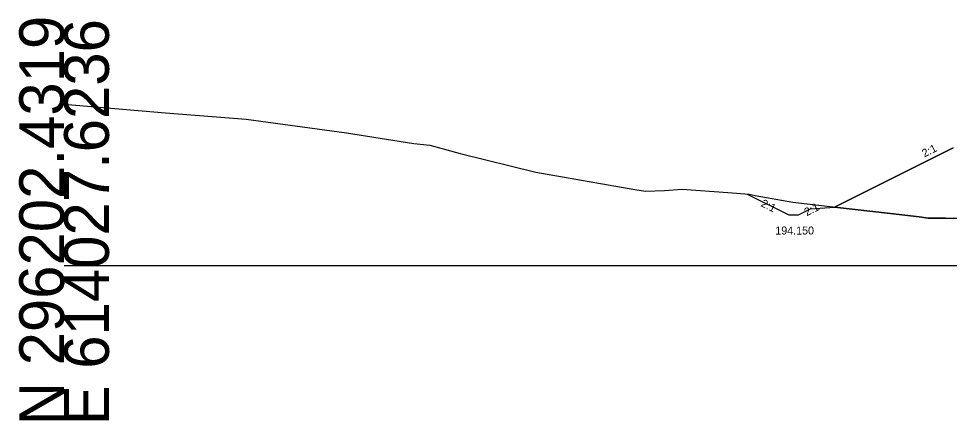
# Model space of a CAD drawing. Extents: x -81 to 616364, y 450 to 299952.
# Drawn here: x 541449.5 to 541507.7, y 118838.7 to 118863.8 of the extents above; entities that cross this region are included whole.
import ezdxf

# ---------------------------------------------------------------- set-up
doc = ezdxf.new("R2010")
doc.units = 0
for name, color, linetype in [('Exist XS Ground Line', 7, 'Continuous'), ('Old_Level_63', 7, 'Continuous'), ('Prop XS DDE', 7, 'Continuous'), ('Prop XS Earthwork Shape', 7, 'Continuous'), ('Prop XS Finish Grade Earthwork', 7, 'Continuous'), ('Prop XS Hydro Elevations', 7, 'Continuous'), ('Prop XS Side Slope Text', 7, 'Continuous')]:
    doc.layers.add(name, color=color, linetype=linetype)

msp = doc.modelspace()

# ---------------------------------------------------------------- linework, layer by layer
at = {"layer": 'Exist XS Ground Line'}
for p, q in [((541452.365, 118858.443), (541458.691, 118857.913)), ((541458.691, 118857.913), (541463.734, 118857.517)), ((541463.734, 118857.517), (541470.016, 118856.654)), ((541470.016, 118856.654), (541474.212, 118855.992)), ((541474.212, 118855.992), (541475.205, 118855.887)), ((541475.205, 118855.887), (541477.115, 118855.353)), ((541477.115, 118855.353), (541481.827, 118854.203)), ((541481.827, 118854.203), (541488.023, 118853.108)), ((541488.023, 118853.108), (541488.696, 118853.001)), ((541488.696, 118853.001), (541489.88, 118853.039)), ((541489.88, 118853.039), (541490.972, 118853.132)), ((541490.972, 118853.132), (541493.826, 118852.927)), ((541493.826, 118852.927), (541495.166, 118852.811)), ((541495.166, 118852.811), (541495.531, 118852.739)), ((541495.531, 118852.739), (541497.888, 118852.314)), ((541497.888, 118852.314), (541503.985, 118851.612)), ((541503.985, 118851.612), (541505.779, 118851.4)), ((541505.779, 118851.4), (541506.345, 118851.32)), ((541506.345, 118851.32), (541507.431, 118851.309)), ((541507.431, 118851.309), (541511.535, 118851.293))]:
    msp.add_line(p, q, dxfattribs=at)
at = {"layer": 'Old_Level_63'}
msp.add_line((541452.365, 118848.365), (541527.365, 118848.365), dxfattribs=at)
at = {"layer": 'Prop XS DDE'}
for p, q in [((541495.034, 118852.822), (541497.649, 118851.515)), ((541498.249, 118851.515), (541499.005, 118851.893)), ((541499.005, 118851.893), (541500.505, 118852.013)), ((541497.649, 118851.515), (541498.249, 118851.515))]:
    msp.add_line(p, q, dxfattribs=at)
at = {"layer": 'Prop XS Earthwork Shape'}
for points in [[(541507.915, 118855.718), (541500.505, 118852.013), (541503.985, 118851.612), (541505.779, 118851.4), (541506.345, 118851.32), (541507.431, 118851.309), (541511.535, 118851.293)], [(541507.915, 118855.718), (541500.505, 118852.013), (541503.985, 118851.612), (541505.779, 118851.4), (541506.345, 118851.32), (541507.431, 118851.309), (541511.535, 118851.293)], [(541511.535, 118851.293), (541507.431, 118851.309), (541506.345, 118851.32), (541505.779, 118851.4), (541503.985, 118851.612), (541500.505, 118852.013), (541507.915, 118855.718)], [(541511.535, 118851.293), (541507.431, 118851.309), (541506.345, 118851.32), (541505.779, 118851.4), (541503.985, 118851.612), (541500.505, 118852.013), (541507.915, 118855.718)]]:
    msp.add_lwpolyline(points, dxfattribs=at)
at = {"layer": 'Prop XS Finish Grade Earthwork'}
msp.add_line((541507.916, 118855.718), (541500.505, 118852.013), dxfattribs=at)

# ---------------------------------------------------------------- texts
at = {"layer": 'Old_Level_63'}
for s, p in [('N 296202.4319', (541452.365, 118838.365)), ('E 614027.6236', (541455.165, 118838.364))]:
    msp.add_text(s, height=2.8, rotation=90, dxfattribs=at).set_placement(p)
at = {"layer": 'Prop XS Hydro Elevations'}
for rotation, p in [(333.43495, (541495.853, 118852.077)), (26.56505, (541498.761, 118851.435))]:
    msp.add_text('2:1', height=0.5, rotation=rotation, dxfattribs=at).set_placement(p)
msp.add_text('194.150', height=0.5, dxfattribs=at).set_placement((541496.798, 118850.295))
at = {"layer": 'Prop XS Side Slope Text'}
msp.add_text('2:1', height=0.5, rotation=26.56512, dxfattribs=at).set_placement((541506.111, 118855.11))

doc.saveas('drawing.dxf')
